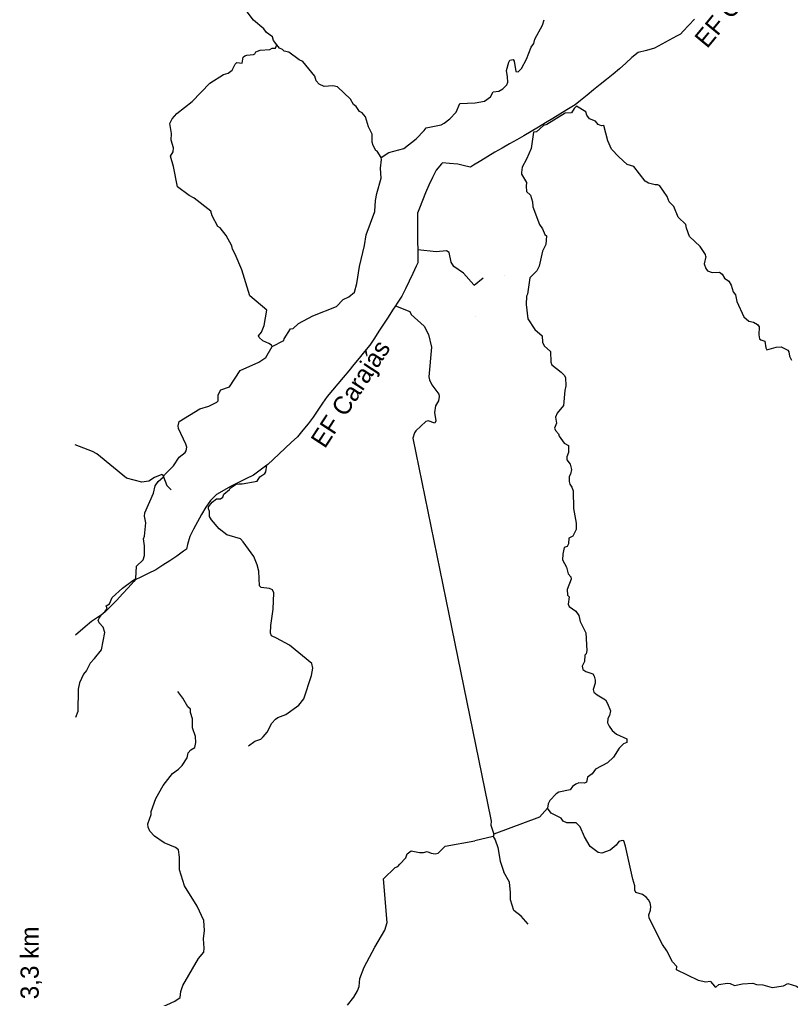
# Model space of a CAD drawing. Extents: x 332 to 501, y 9447 to 9559.
# Drawn here: x 332.35 to 348.5, y 9526 to 9546.5 of the extents above; entities that cross this region are included whole.
import ezdxf

# ---------------------------------------------------------------- set-up
doc = ezdxf.new("R2010")
doc.units = 0
for name, color, linetype in [('Level 12', 7, 'Continuous'), ('Level 22', 7, 'Continuous'), ('Level 31', 7, 'Continuous'), ('Level 4', 7, 'Continuous'), ('Level 5', 7, 'Continuous'), ('Level 6', 7, 'Continuous')]:
    doc.layers.add(name, color=color, linetype=linetype)

msp = doc.modelspace()

# ---------------------------------------------------------------- linework, layer by layer
at = {"layer": 'Level 22'}
for points in [[(346.3688, 9546.3863), (346.2484, 9546.2594)], [(346.4892, 9546.5133), (346.3688, 9546.3863)], [(346.11, 9546.1556), (345.9569, 9546.0708)], [(346.2484, 9546.2594), (346.194, 9546.2021), (346.11, 9546.1556)], [(345.8038, 9545.9861), (345.6504, 9545.9021)], [(345.9569, 9546.0708), (345.8038, 9545.9861)], [(345.3108, 9545.8172), (345.1758, 9545.7097)], [(345.4806, 9545.8596), (345.3108, 9545.8172)], [(345.6504, 9545.9021), (345.4806, 9545.8596)], [(345.0462, 9545.5921), (344.9166, 9545.4746)], [(345.1758, 9545.7097), (345.0462, 9545.5921)], [(344.7828, 9545.3619), (344.6468, 9545.2518)], [(344.9166, 9545.4746), (344.7828, 9545.3619)], [(344.5107, 9545.1417), (344.3747, 9545.0316)], [(344.6468, 9545.2518), (344.5107, 9545.1417)], [(344.2386, 9544.9215), (344.1026, 9544.8114)], [(344.3747, 9545.0316), (344.2386, 9544.9215)], [(343.9842, 9544.7156), (343.8153, 9544.6128)], [(344.1026, 9544.8114), (343.9842, 9544.7156)], [(343.6658, 9544.5219), (343.5163, 9544.4309)], [(343.8153, 9544.6128), (343.6658, 9544.5219)], [(343.3668, 9544.34), (343.2172, 9544.2491)], [(343.5163, 9544.4309), (343.3668, 9544.34)], [(343.0675, 9544.1586), (342.9154, 9544.0719)], [(343.2172, 9544.2491), (343.0675, 9544.1586)], [(342.6113, 9543.8987), (342.4592, 9543.8121)], [(342.7634, 9543.9853), (342.6113, 9543.8987)], [(342.9154, 9544.0719), (342.7634, 9543.9853)], [(342.3072, 9543.7255), (342.1568, 9543.636)], [(342.4592, 9543.8121), (342.3072, 9543.7255)], [(341.1898, 9543.4826), (341.0759, 9543.3497)], [(341.3555, 9543.4907), (341.2062, 9543.5018), (341.1898, 9543.4826)], [(341.53, 9543.4778), (341.3555, 9543.4907)], [(342.0081, 9543.5438), (341.8593, 9543.4516)], [(342.1568, 9543.636), (342.0081, 9543.5438)], [(341.0759, 9543.3497), (340.995, 9543.196)], [(341.6996, 9543.4365), (341.53, 9543.4778)], [(341.8593, 9543.4516), (341.7931, 9543.4105), (341.6996, 9543.4365)], [(340.995, 9543.196), (340.924, 9543.0361)], [(340.853, 9542.8761), (340.7885, 9542.7135)], [(340.924, 9543.0361), (340.853, 9542.8761)], [(340.7885, 9542.7135), (340.7253, 9542.5502)], [(340.7253, 9542.5502), (340.6846, 9542.4449), (340.6849, 9542.3828)], [(340.6849, 9542.3828), (340.6857, 9542.2078)], [(340.6857, 9542.2078), (340.6865, 9542.0328)], [(340.6865, 9542.0328), (340.6873, 9541.8579)], [(340.6873, 9541.8579), (340.6881, 9541.6829)], [(340.6881, 9541.6829), (340.6881, 9541.6772)], [(340.6881, 9541.6772), (340.6889, 9541.5079)], [(340.6889, 9541.5079), (340.6894, 9541.4072), (340.6577, 9541.34)], [(340.6577, 9541.34), (340.583, 9541.1817)], [(340.5084, 9541.0234), (340.4337, 9540.8652)], [(340.583, 9541.1817), (340.5084, 9541.0234)], [(340.4337, 9540.8652), (340.3573, 9540.7079)], [(340.3573, 9540.7079), (340.2603, 9540.5623)], [(340.1632, 9540.4166), (340.0662, 9540.2709)], [(340.2245, 9540.5086), (340.1632, 9540.4166)], [(340.2603, 9540.5623), (340.2245, 9540.5086)], [(340.0662, 9540.2709), (339.9693, 9540.1252)], [(339.9693, 9540.1252), (339.8754, 9539.9776)], [(339.7815, 9539.8299), (339.6853, 9539.6839)], [(339.8754, 9539.9776), (339.7815, 9539.8299)], [(339.6853, 9539.6839), (339.5746, 9539.5484)], [(339.4638, 9539.4129), (339.353, 9539.2774)], [(339.5746, 9539.5484), (339.4638, 9539.4129)], [(339.353, 9539.2774), (339.2423, 9539.1419)], [(339.129, 9539.0085), (339.0154, 9538.8754)], [(339.2423, 9539.1419), (339.129, 9539.0085)], [(339.0154, 9538.8754), (338.9018, 9538.7423)], [(338.7882, 9538.6092), (338.69, 9538.4645)], [(338.9018, 9538.7423), (338.7882, 9538.6092)], [(338.69, 9538.4645), (338.5939, 9538.3182)], [(338.4979, 9538.1719), (338.3901, 9538.0343)], [(338.5939, 9538.3182), (338.4979, 9538.1719)], [(338.3901, 9538.0343), (338.2786, 9537.8994)], [(338.1671, 9537.7646), (338.0403, 9537.6441)], [(338.2786, 9537.8994), (338.1671, 9537.7646)], [(338.0403, 9537.6441), (337.9126, 9537.5243)], [(337.785, 9537.4046), (337.6574, 9537.2849)], [(337.9126, 9537.5243), (337.785, 9537.4046)], [(337.5292, 9537.1658), (337.3893, 9537.0608)], [(337.545, 9537.1805), (337.5292, 9537.1658)], [(337.6574, 9537.2849), (337.545, 9537.1805)], [(337.2463, 9536.9605), (337.0898, 9536.8822)], [(337.3893, 9537.0608), (337.2463, 9536.9605)], [(336.7767, 9536.7257), (336.4735, 9536.5516)], [(337.0898, 9536.8822), (336.7767, 9536.7257)], [(336.4735, 9536.5516), (336.3498, 9536.4279)], [(336.3498, 9536.4279), (336.2497, 9536.2853)], [(336.1574, 9536.1366), (336.0751, 9535.9822)], [(336.2497, 9536.2853), (336.1574, 9536.1366)], [(336.0751, 9535.9822), (335.9927, 9535.8278)], [(335.9927, 9535.8278), (335.9103, 9535.6733)], [(335.8627, 9535.5061), (335.8403, 9535.4051), (335.7816, 9535.3642)], [(335.9103, 9535.6733), (335.8627, 9535.5061)], [(335.7816, 9535.3642), (335.638, 9535.2642)], [(335.4934, 9535.1656), (335.347, 9535.0698)], [(335.638, 9535.2642), (335.4934, 9535.1656)], [(335.043, 9534.8977), (334.8856, 9534.8213)], [(335.2004, 9534.9741), (335.043, 9534.8977)], [(335.347, 9535.0698), (335.2004, 9534.9741)], [(334.7393, 9534.7301), (334.6228, 9534.5996)], [(334.8856, 9534.8213), (334.771, 9534.7657), (334.7393, 9534.7301)], [(334.5062, 9534.469), (334.3863, 9534.3417)], [(334.6228, 9534.5996), (334.5062, 9534.469)], [(334.3863, 9534.3417), (334.2626, 9534.2179)], [(334.1389, 9534.0941), (334.0574, 9534.0244)], [(334.2626, 9534.2179), (334.1389, 9534.0941)], [(333.8558, 9533.8899), (333.7208, 9533.7801)], [(334.0014, 9533.987), (333.8558, 9533.8899)], [(334.0574, 9534.0244), (334.0014, 9533.987)], [(333.7208, 9533.7801), (333.5176, 9533.6068)]]:
    msp.add_lwpolyline(points, dxfattribs=at)
at = {"layer": 'Level 4'}
for points in [[(337.7398, 9545.9727), (337.6672, 9546.0635), (337.6445, 9546.1407), (337.522, 9546.2361), (337.4675, 9546.3133), (337.2496, 9546.4905), (336.9455, 9546.8901)], [(337.2995, 9545.8253), (337.3903, 9545.8617), (337.5901, 9545.8753), (337.64, 9545.9071), (337.7081, 9545.9071), (337.7398, 9545.9727)], [(339.9217, 9543.6169), (339.8384, 9543.7445), (339.8098, 9543.7627), (339.7526, 9543.864), (339.737, 9543.9368), (339.737, 9544.1005), (339.6565, 9544.259), (339.5915, 9544.4642), (339.5214, 9544.55), (339.4668, 9544.576), (339.3967, 9544.6845), (339.3421, 9544.7287), (339.2823, 9544.8353), (339.0095, 9545.0927), (338.9133, 9545.1187), (338.7289, 9545.1057), (338.6207, 9545.1539), (338.561, 9545.2189), (338.5298, 9545.3177), (338.2829, 9545.6245), (338.205, 9545.6635), (337.9867, 9545.8221), (337.888, 9545.8403), (337.8542, 9545.8767), (337.7944, 9545.9027), (337.7398, 9545.9727)], [(337.6354, 9539.6568), (337.6218, 9539.6841), (337.5674, 9539.7158), (337.4403, 9539.7703), (337.3631, 9539.8429), (337.354, 9539.8747), (337.413, 9539.9519), (337.472, 9540.0926), (337.5265, 9540.4148), (337.1679, 9540.719), (337, 9541.2591), (336.8638, 9541.5889), (336.8048, 9541.6934), (336.7912, 9541.7615), (336.6731, 9541.9795), (336.5461, 9542.1385), (336.5007, 9542.1657), (336.3826, 9542.3928), (336.3554, 9542.4927), (336.0059, 9542.7652), (335.897, 9542.8197), (335.6564, 9542.9969), (335.5747, 9543.4258), (335.5066, 9543.6438), (335.5656, 9543.7346), (335.5701, 9543.8164), (335.5248, 9543.9753), (335.5293, 9544.1207), (335.4975, 9544.3251), (335.5429, 9544.425), (335.6428, 9544.534), (335.9605, 9544.7898), (336.3327, 9545.1713), (336.6187, 9545.353), (336.714, 9545.3803), (336.8002, 9545.4438), (336.8638, 9545.571), (336.8956, 9545.6028), (337.009, 9545.5892), (337.0317, 9545.7163), (337.0635, 9545.7436), (337.1089, 9545.7618), (337.2451, 9545.7754), (337.2769, 9545.789), (337.2995, 9545.8253)], [(337.6354, 9539.6568), (337.8855, 9539.7805), (337.8935, 9539.8165), (338.0253, 9540.0243), (338.0772, 9540.0323), (338.193, 9540.1363), (338.4886, 9540.3001), (338.9868, 9540.4947), (339.1266, 9540.6426), (339.2464, 9540.6946), (339.3623, 9540.7945), (339.4102, 9540.9767), (339.4661, 9541.3324), (339.57, 9541.7681), (339.6059, 9541.9919), (339.7897, 9542.4859), (339.8017, 9542.7137), (339.8296, 9542.8616), (339.9215, 9543.1801), (339.9095, 9543.3879), (339.931, 9543.572), (339.9217, 9543.6169)], [(346.7223, 9541.54), (346.6936, 9541.3888), (346.7238, 9541.2897), (346.7582, 9541.2381), (346.8616, 9541.2079), (347.0123, 9541.2122), (347.0683, 9541.1735), (347.12, 9541.0873), (347.2105, 9541.0227), (347.2597, 9540.9388), (347.2966, 9540.803), (347.344, 9540.7384), (347.3721, 9540.5964), (347.5206, 9540.2776), (347.6282, 9540.1871), (347.723, 9540.1613), (347.8091, 9540.1139), (347.8436, 9540.0665), (347.835, 9539.8986), (347.8479, 9539.8167), (347.8781, 9539.7909), (347.9642, 9539.7693), (347.9801, 9539.6293), (348.0016, 9539.5862), (348.1997, 9539.6422), (348.3074, 9539.6508), (348.4409, 9539.5775), (348.4624, 9539.5431), (348.4754, 9539.4526), (348.5227, 9539.3707)], [(340.2245, 9540.5086), (340.524, 9540.386), (340.554, 9540.324), (340.825, 9540.081), (340.915, 9539.905), (340.976, 9539.642), (340.923, 9539.018), (340.934, 9538.954), (340.986, 9538.851), (341.128, 9538.654), (341.141, 9538.605), (341.124, 9538.513), (341.063, 9538.408), (341.038, 9538.273), (341.068, 9538.096), (341.048, 9538.047), (340.908, 9538.097), (340.857, 9538.083), (340.648, 9537.889), (340.618, 9537.847), (340.583, 9537.737), (341.34, 9534.048)], [(337.5038, 9539.4253), (337.6354, 9539.6568)], [(335.6927, 9538.0854), (336.1209, 9538.3512), (336.3126, 9538.4071), (336.4764, 9538.4871), (336.5084, 9538.515), (336.5084, 9538.6429), (336.5603, 9538.7469), (336.744, 9538.8068), (336.9717, 9539.1545), (337.3592, 9539.3264), (337.5038, 9539.4253)], [(335.3585, 9536.9219), (335.3856, 9536.9684), (335.5744, 9537.1521), (335.6927, 9537.3384), (335.816, 9537.434), (335.8386, 9537.4718), (335.8512, 9537.5422), (335.8311, 9537.6051), (335.6776, 9537.9394), (335.6725, 9537.9923), (335.6927, 9538.0854)], [(334.7182, 9534.7489), (334.7791, 9534.7928), (334.7984, 9535.0535), (334.9368, 9535.1815), (334.9658, 9535.2749), (334.9658, 9535.4811), (334.94, 9535.6228), (334.9626, 9535.684), (334.9883, 9535.9599), (334.9626, 9536.0984), (334.969, 9536.1693), (335.1493, 9536.5805), (335.1879, 9536.7383), (335.2523, 9536.8285), (335.3585, 9536.9219)], [(334.162, 9534.218), (334.2319, 9534.2617), (334.2866, 9534.3969), (334.5023, 9534.5932), (334.7182, 9534.7489)], [(334.0574, 9534.0244), (334.1349, 9534.0981)], [(334.1349, 9534.0981), (334.179, 9534.164), (334.162, 9534.218)], [(341.34, 9534.048), (342.215, 9529.782), (342.228, 9529.707), (342.22, 9529.625), (342.2813, 9529.4342)], [(333.916, 9533.118), (334.065, 9533.299), (334.13, 9533.661), (334.095, 9533.775), (334.017, 9533.865), (333.995, 9533.918), (334.0158, 9533.9654)], [(334.0158, 9533.9654), (334.0574, 9534.0244)], [(333.916, 9533.118), (333.8265, 9533.0208), (333.745, 9532.8668), (333.6876, 9532.7913), (333.6031, 9532.6041), (333.573, 9532.4772), (333.5639, 9532.0039), (333.521, 9531.8823)], [(336.093, 9526.829), (336.205, 9526.9655), (336.2151, 9527.0507), (336.2, 9527.246), (336.2201, 9527.4214), (336.205, 9527.6267), (336.0698, 9527.9273), (335.7993, 9528.3519), (335.6991, 9528.6927), (335.6991, 9528.9533), (335.6741, 9529.1087), (335.614, 9529.1588), (335.3786, 9529.257), (335.1732, 9529.3923), (335.073, 9529.4976), (335.038, 9529.5828), (335.0329, 9529.6529), (335.1031, 9529.8484), (335.1031, 9529.9136), (335.2032, 9530.1842), (335.3535, 9530.4549), (335.5489, 9530.7105), (335.6791, 9530.7976), (335.7542, 9530.8778), (335.8544, 9531.0381), (335.8795, 9531.1384), (335.9346, 9531.2035), (336.0197, 9531.2537), (336.0398, 9531.3589), (336.0347, 9531.4841), (335.9696, 9531.6645), (335.9696, 9531.8549), (335.9296, 9531.9853), (335.9245, 9532.0554), (335.8745, 9532.1055), (335.7693, 9532.286), (335.6651, 9532.4262)], [(342.271, 9529.387), (341.887, 9529.297)], [(342.2813, 9529.4342), (342.271, 9529.387)], [(340.3165, 9528.8076), (340.4427, 9528.9443), (340.4709, 9529.0218), (340.5484, 9529.0852), (340.7245, 9529.05), (340.809, 9529.05), (340.8865, 9529.0711), (340.971, 9529.0359), (341.0556, 9529.0218), (341.119, 9529.0359), (341.2669, 9529.1838), (341.887, 9529.297)], [(339.2202, 9525.8532), (339.3509, 9526.0211), (339.4284, 9526.1549), (339.4636, 9526.2465), (339.4777, 9526.4155), (339.5693, 9526.648), (339.7876, 9527.0706), (339.999, 9527.4228), (340.0483, 9527.5848), (339.9708, 9528.5005), (340.2173, 9528.74), (340.2737, 9528.7612), (340.3165, 9528.8076)], [(335.909, 9524.309), (335.913, 9524.367), (335.938, 9524.393), (335.929, 9524.417), (335.292, 9524.697), (335.13, 9524.716), (335.084, 9524.893), (335.083, 9524.998), (335.139, 9525.23), (335.167, 9525.477), (335.222, 9525.649), (335.233, 9525.738), (335.262, 9525.787), (335.6, 9525.941), (335.708, 9526.015), (335.724, 9526.14), (335.764, 9526.266), (336.093, 9526.829)]]:
    msp.add_lwpolyline(points, dxfattribs=at)
at = {"layer": 'Level 5'}
for points in [[(342.2683, 9544.9886), (342.387, 9545.0061), (342.4709, 9545.0501), (342.5587, 9545.134), (342.5747, 9545.194), (342.5707, 9545.3059), (342.5468, 9545.4378), (342.5947, 9545.6137), (342.6187, 9545.6536), (342.6906, 9545.6696), (342.7105, 9545.6336), (342.7465, 9545.4178), (342.7944, 9545.4098), (342.8623, 9545.4818), (342.9662, 9545.6776), (343.0689, 9545.9242), (343.1248, 9546.0041), (343.1448, 9546.0921), (343.3046, 9546.3878), (343.3365, 9546.4959)], [(340.8223, 9544.1813), (340.8623, 9544.2332), (341.1778, 9544.3012), (341.2457, 9544.3371), (341.3616, 9544.4251), (341.4934, 9544.5649), (341.5733, 9544.7448), (341.8888, 9544.7568), (342.0886, 9544.7928), (342.2124, 9544.8887), (342.2683, 9544.9886)], [(344.0164, 9544.6909), (343.9632, 9544.6433), (343.911, 9544.5534), (343.7804, 9544.5418), (343.3916, 9544.3038), (343.3249, 9544.2864), (343.1769, 9544.153), (343.113, 9544.1443), (343.0637, 9543.8048), (342.968, 9543.5813), (342.8751, 9543.4101), (342.8616, 9543.3018), (342.8616, 9543.267), (342.969, 9543.0898), (342.9574, 9543.0172), (342.969, 9542.904), (343.0531, 9542.8285), (343.0938, 9542.6891), (343.1025, 9542.5817), (343.2418, 9542.2089), (343.3056, 9542.1189), (343.3491, 9542.0027), (343.3839, 9541.9708), (343.3752, 9541.7937), (343.3027, 9541.6555), (343.2301, 9541.339), (343.1866, 9541.2432), (343.0357, 9541.0951), (342.9893, 9540.7543), (342.9661, 9540.7078), (342.9632, 9540.5336), (342.998, 9540.2374), (343.1431, 9540.008), (343.2935, 9539.8765), (343.3051, 9539.7488), (343.3399, 9539.6675), (343.4734, 9539.5513), (343.4763, 9539.3277), (343.4966, 9539.2696), (343.691, 9539.1186), (343.7635, 9539.046), (343.7867, 9538.9967), (343.7925, 9538.8282), (343.7693, 9538.7343), (343.7432, 9538.4178), (343.6126, 9538.258), (343.5749, 9538.1738), (343.5981, 9538.0505), (343.5575, 9537.9431), (343.5749, 9537.8937), (343.6417, 9537.8269), (343.6533, 9537.7775)], [(346.7223, 9541.54), (346.717, 9541.584), (346.61, 9541.752), (346.386, 9541.959), (346.317, 9542.132), (346.309, 9542.208), (346.146, 9542.365), (346.057, 9542.59), (345.96, 9542.685), (345.914, 9542.8), (345.765, 9543.019), (345.717, 9543.044), (345.661, 9543.041), (345.527, 9543.08), (345.454, 9543.116), (345.22, 9543.427), (345.074, 9543.468), (344.901, 9543.626), (344.746, 9543.786), (344.673, 9543.963), (344.59, 9544.285), (344.539, 9544.276), (344.469, 9544.309), (344.411, 9544.379), (344.285, 9544.428), (344.231, 9544.502), (344.209, 9544.572), (344.0164, 9544.6909)], [(339.9217, 9543.6169), (340.0833, 9543.7176), (340.3949, 9543.8056), (340.6546, 9544.0054), (340.8223, 9544.1813)], [(343.6533, 9537.7775), (343.7577, 9537.6294), (343.8477, 9537.583), (343.8477, 9537.4358)], [(335.3585, 9536.9219), (335.3542, 9536.961), (335.3291, 9536.9761), (335.173, 9536.9106), (335.0572, 9536.8351), (334.9062, 9536.8149), (334.5891, 9536.8955), (333.965, 9537.4042), (333.8744, 9537.4546), (333.5101, 9537.5945)], [(343.8477, 9537.4358), (343.81, 9537.3458), (343.81, 9537.279), (343.8825, 9537.1861), (343.9115, 9537.0786), (343.8912, 9536.977), (343.8651, 9536.9305), (343.8651, 9536.8289), (343.8767, 9536.7679), (343.9202, 9536.704), (343.9434, 9536.6333), (343.955, 9536.2587), (344.0102, 9535.9509), (344.0073, 9535.8231), (343.9376, 9535.6835), (343.8564, 9535.637), (343.8448, 9535.5208), (343.8176, 9535.4671), (343.7583, 9535.4463), (343.7257, 9535.3068), (343.7227, 9535.188), (343.8058, 9535.0307), (343.8384, 9534.8941), (343.8977, 9534.8259), (343.9037, 9534.7784), (343.8206, 9534.5662), (343.8295, 9534.4474), (343.8651, 9534.4088), (343.8443, 9534.2545), (343.8651, 9534.204), (344.0015, 9534.112), (344.0609, 9534.0199), (344.0935, 9533.8952), (344.2092, 9533.6518), (344.2354, 9533.2832), (344.2205, 9533.2179), (344.1879, 9533.1852), (344.182, 9533.0546), (344.1375, 9532.9537), (344.1493, 9532.8884), (344.2087, 9532.8468), (344.357, 9532.7934), (344.3866, 9532.7468), (344.4074, 9532.6666), (344.4044, 9532.6013), (344.3659, 9532.4707), (344.3807, 9532.4143), (344.4489, 9532.3549), (344.6239, 9532.248), (344.6684, 9532.1738)], [(336.9457, 9536.7791), (337.007, 9536.7754), (337.3223, 9536.8305), (337.3774, 9536.9257), (337.4825, 9536.9958), (337.5076, 9537.0309), (337.5292, 9537.1658)], [(335.3585, 9536.9219), (335.4337, 9536.741), (335.5211, 9536.648)], [(336.7569, 9536.6892), (336.8868, 9536.7704), (336.9457, 9536.7791)], [(336.6855, 9535.7061), (336.5278, 9535.8348), (336.3676, 9536.02), (336.3275, 9536.0951), (336.3275, 9536.1952), (336.3025, 9536.2503), (336.3025, 9536.2953), (336.3826, 9536.3955), (336.4727, 9536.4655), (336.5578, 9536.4655), (336.6029, 9536.4956), (336.6279, 9536.5607), (336.743, 9536.6558), (336.7569, 9536.6892)], [(337.732, 9533.544), (337.622, 9533.59), (337.605, 9533.647), (337.612, 9533.808), (337.662, 9534.151), (337.673, 9534.496), (337.647, 9534.556), (337.586, 9534.586), (337.411, 9534.607), (337.37, 9534.643), (337.358, 9534.948), (337.327, 9535.081), (337.258, 9535.253), (337.033, 9535.562), (336.975, 9535.624), (336.6855, 9535.7061)], [(337.142, 9531.2842), (337.2732, 9531.3843), (337.403, 9531.428), (337.451, 9531.474), (337.533, 9531.575), (337.63, 9531.759), (337.707, 9531.844), (337.757, 9531.883), (337.922, 9531.946), (338.1961, 9532.1378), (338.299, 9532.273), (338.465, 9532.764), (338.493, 9532.918), (338.471, 9533.011), (338.003, 9533.395), (337.732, 9533.544)], [(344.6684, 9532.1738), (344.727, 9532.0216), (344.7062, 9531.9236), (344.6736, 9531.8583), (344.6647, 9531.7663), (344.6973, 9531.7009), (344.7596, 9531.606), (344.8516, 9531.5317), (345.0675, 9531.4338)], [(345.0675, 9531.4338), (345.0681, 9531.3605), (345.0028, 9531.3278), (344.9079, 9531.2417), (344.7893, 9531.0488), (344.6617, 9530.93), (344.4155, 9530.7994), (344.3414, 9530.7014), (344.2435, 9530.6302), (344.2257, 9530.5292), (344.1822, 9530.507), (344.0665, 9530.51), (344.0043, 9530.4863), (343.9301, 9530.4388), (343.8856, 9530.3645), (343.6424, 9530.317), (343.589, 9530.2814), (343.4585, 9530.1389), (343.4229, 9530.0706), (343.4082, 9529.9799)], [(343.4082, 9529.9799), (343.2368, 9529.7925), (342.2813, 9529.4342)], [(342.271, 9529.387), (342.3123, 9529.3211), (342.3693, 9529.154), (342.4187, 9528.8691), (342.4935, 9528.6399)], [(343.0051, 9527.5517), (342.854, 9527.7196), (342.7028, 9527.838), (342.6356, 9528.0639), (342.6356, 9528.2151), (342.6104, 9528.4334), (342.4935, 9528.6399)]]:
    msp.add_lwpolyline(points, dxfattribs=at)
at = {"layer": 'Level 6'}
for p, q in [((342.4994, 9541.1442), (342.4994, 9541.1442)), ((341.8961, 9540.2875), (341.8961, 9540.2875))]:
    msp.add_line(p, q, dxfattribs=at)
for points in [[(341.8617, 9540.9464), (341.8617, 9540.9464), (341.6449, 9541.1911), (341.4422, 9541.3309), (341.3863, 9541.4218), (341.3444, 9541.6245), (341.2884, 9541.6595), (341.0717, 9541.6385), (340.6881, 9541.6829)], [(341.8617, 9540.9464), (341.8719, 9540.9391), (342.0589, 9541.096)], [(346.82, 9526.353), (346.719, 9526.336), (346.573, 9526.37), (346.113, 9526.597), (346.117, 9526.661), (346.028, 9526.763), (345.909, 9526.992), (345.819, 9527.122), (345.539, 9527.677), (345.534, 9527.75), (345.569, 9527.842), (345.572, 9527.918), (345.56, 9527.995), (345.527, 9528.063), (345.478, 9528.118), (345.395, 9528.17), (345.259, 9528.216), (345.24, 9528.262), (345.238, 9528.357), (345.193, 9528.495), (345.044, 9529.188), (345.005, 9529.296), (344.971, 9529.305), (344.9, 9529.28), (344.847, 9529.205), (344.723, 9529.1), (344.546, 9529.04), (344.467, 9529.053), (344.301, 9529.177), (344.182, 9529.383), (344.089, 9529.588), (344.007, 9529.674), (343.813, 9529.674), (343.734, 9529.707), (343.694, 9529.773), (343.485, 9529.875), (343.4082, 9529.9799)], [(346.82, 9526.353), (346.907, 9526.255)], [(346.907, 9526.255), (346.935, 9526.234), (346.996, 9526.284), (347.172, 9526.312), (347.238, 9526.308), (347.329, 9526.264), (347.493, 9526.302), (347.709, 9526.313), (347.786, 9526.288), (347.921, 9526.278), (348.113, 9526.223), (348.353, 9526.261), (348.445, 9526.308), (348.623, 9526.252), (348.701, 9526.197), (348.92, 9526.137), (348.975, 9526.162), (349.002, 9526.202), (349.049, 9526.33)]]:
    msp.add_lwpolyline(points, dxfattribs=at)

# ---------------------------------------------------------------- texts
at = {"layer": 'Level 12'}
msp.add_text('Verona 3,3 km', height=0.38, rotation=90, dxfattribs=at).set_placement((332.7464, 9524.1976))
at = {"layer": 'Level 31'}
for rotation, p in [(50.38046, (346.7521, 9545.8833)), (56.81976, (338.742, 9537.4996))]:
    msp.add_text('EF Carajás', height=0.38, rotation=rotation, dxfattribs=at).set_placement(p)

doc.saveas('drawing.dxf')
